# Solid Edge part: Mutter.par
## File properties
Sűrűség: 0,000 kg/m^3
Pontosság: 0,990
Author: ahadarics
Last saved by: psaghy
Revision: 78
Username: ahadarics
Dokumentum tartalom típus: 0
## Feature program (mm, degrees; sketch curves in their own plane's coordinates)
base feature "unnamed BaseFeature 1"
sketch for "Furat_1" plane through (6, 0, 0) normal (1, 0, 0) x-axis (0, -1, 0)
  hole centre (0, 0) bore radius 4.3235
hole "Furat_1" through  StartChamferOffset = 0.39 mm; StartChamferAngle = 45 deg; EndChamferOffset = 0.39 mm; EndChamferAngle = 45 deg
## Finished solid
Body 1: solid body, 23 faces, 46 edges, 24 vertices.
  Faces by surface: cone 14, plane 8, cylinder 1
  Edges by curve: spline 24, circle 16, line 6
Bounding box of the edges (mm): 6.000 x 19.630 x 17.000, from (0, -9.815, -8.5) to (6, 9.815, 8.5).
Cylindrical faces by radius (mm): R4.3235 x1
Conical faces (half-angle, radius in mm at the cone's reference point): 45 deg R4.7135 x2, 60 deg R9.1575 x12
Planar faces by outward normal: +x 1, +z 1, -x 1, -z 1, oblique 4
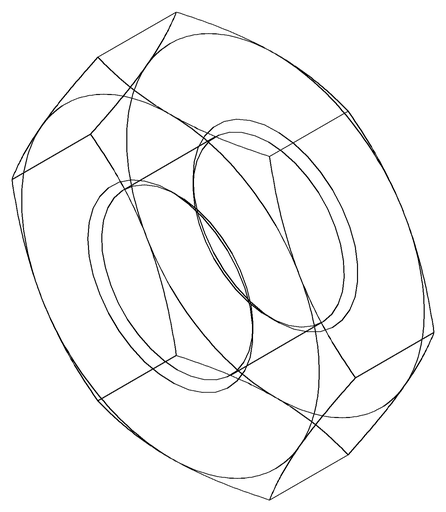
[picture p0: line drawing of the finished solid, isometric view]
